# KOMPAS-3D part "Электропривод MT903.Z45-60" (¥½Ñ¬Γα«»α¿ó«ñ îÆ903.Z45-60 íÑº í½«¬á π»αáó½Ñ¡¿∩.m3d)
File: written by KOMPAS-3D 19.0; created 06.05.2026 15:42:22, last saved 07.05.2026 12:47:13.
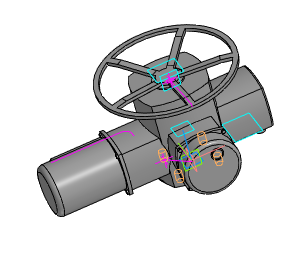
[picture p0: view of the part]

Document properties: Автор: Энергия; Полное имя файла: Z:\3.Личные\kachalov\3d для проектировщиков\2.2 Тип 47GVA, 47GVA.Z\Привод\Электропривод МТ903.Z45-60 без блока управления.m3d

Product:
- Part/product: Электропривод MT903.Z45-60
    Масса: 170.293

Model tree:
1. Эскиз:1
2. Элемент выдавливания:1
     Расстояние 1 = 274
3. Эскиз:2
4. Элемент выдавливания:2
     Расстояние 1 = 200
5. Эскиз:3  (with: Элемент выдавливания:2)
6. Элемент выдавливания:3
     Расстояние 1 = 10
7. Эскиз:4  (with: Элемент выдавливания:3)
8. Элемент выдавливания:4
     Расстояние 1 = 200
9. Скругление:1  (with: Элемент выдавливания:4)
     Радиус = 15
10. Эскиз:5
11. Элемент выдавливания:5
     Расстояние 1 = 170
12. Эскиз:6  (with: Элемент выдавливания:5)
13. Элемент выдавливания:6
     Расстояние 1 = 10
14. Эскиз:7  (with: Элемент выдавливания:6)
15. Элемент выдавливания:7
     Расстояние 1 = 50
16. Скругление:2  (with: Элемент выдавливания:7)
     Радиус = 10
17. Эскиз:8
18. Элемент выдавливания:8
     Расстояние 1 = 230
19. Скругление:3  (with: Элемент выдавливания:8)
     Радиус = 5
20. Касательная плоскость:1  (with: Элемент выдавливания:8)
21. Эскиз:10
22. Элемент выдавливания:9
     Расстояние 1 = 5
23. Эскиз:11  (with: Элемент выдавливания:9)
24. Отверстие:1  (with: Элемент выдавливания:9)  (labels: M20)
     Глубина выреза = 35; Диаметр отверстия = 17.2937; Угол конуса дна = 118; Расстояние 1 = -58.3363; Расстояние 2 = -58.3363
25. M20  (with: Элемент выдавливания:9)  (labels: M20; cil0_24705-2004 coarse)
     Длина резьбы = 30; Шаг резьбы = 2.5; Номинальный диаметр резьбы = 20
26. Массив по концентрической сетке:1  (with: Отверстие:1, Эскиз:11)  (labels: M20)  (2 pattern instances)
27. M10  (with: Отверстие:1, Элемент выдавливания:9, Эскиз:11)  (labels: M20; cil0_24705-2004 coarse)  (1 pattern instances)
     Длина резьбы = 30; Шаг резьбы = 2.5; Номинальный диаметр резьбы = 20
28. Отверстие:1  (with: Эскиз:11)  (labels: M20)
29. Эскиз:12  (with: Элемент выдавливания:9)
30. Элемент выдавливания:10
     Расстояние 1 = 5
31. Эскиз:13  (with: Элемент выдавливания:10)
32. Элемент выдавливания:11
     Расстояние 2 = 50
33. Эскиз:14
34. Элемент выдавливания:14  (with: Элемент выдавливания:8)
     Расстояние 1 = 15; Расстояние 2 = 10
35. Эскиз:15  (with: Элемент выдавливания:1)
36. Элемент выдавливания:15
     Расстояние 1 = 5
37. Эскиз:16  (with: Элемент выдавливания:15)
38. Смещенная плоскость:1  (with: Элемент выдавливания:15)
     Расстояние = 25
39. Эскиз:17  (with: Элемент выдавливания:15)
40. Элемент выдавливания:16
     Расстояние 1 = 10
41. Элемент выдавливания:17
     Расстояние 1 = 10
42. Эскиз:20  (with: Элемент выдавливания:16, Элемент выдавливания:17)
43. Перпендикулярная плоскость:1
44. Эскиз:21
45. Элемент по траектории:1
46. Массив по концентрической сетке:5  (with: Элемент по траектории:1, Эскиз:21, Элемент выдавливания:17)  (5 pattern instances)
     Шаг 2 = 360
47. Скругление:5  (with: Элемент выдавливания:14, Элемент выдавливания:7, Элемент выдавливания:4)
     Радиус = 1
48. Эскиз:22  (with: Элемент выдавливания:3, Скругление:5)
49. Элемент выдавливания:18
     Расстояние 1 = 5
50. Скругление:6  (with: Элемент выдавливания:18)
     Радиус = 1
51. Массив по концентрической сетке:3  (with: Элемент выдавливания:18, Эскиз:22, Скругление:6, Элемент выдавливания:4)  (4 pattern instances)
     Шаг 2 = 360
52. Эскиз:23  (with: Элемент выдавливания:6, Скругление:5)
53. Элемент выдавливания:19
     Расстояние 1 = 5
54. Скругление:7  (with: Элемент выдавливания:19)
     Радиус = 1
55. Массив по концентрической сетке:4  (with: Элемент выдавливания:19, Эскиз:23, Скругление:7, Элемент выдавливания:7)  (4 pattern instances)
     Шаг 2 = 360
56. Эскиз:24
57. Элемент выдавливания:20
     Расстояние 1 = 60
58. Смещенная плоскость:2
59. Эскиз:25  (with: Элемент выдавливания:20)
60. Эскиз:26  (with: Элемент выдавливания:20)
61. Элемент по траектории:2
62. Фаска:1  (with: Элемент по траектории:2)
     Угол = 45; Длина 1 = 2; Длина 2 = 2
63. Эскиз:27  (with: Элемент выдавливания:7)
64. Элемент выдавливания:21
     Расстояние 1 = 3
65. Эскиз:28  (with: Элемент выдавливания:21)
66. Элемент выдавливания:22
     Расстояние 2 = 1

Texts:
  Точка начала. Х
  Точка начала. Y
  Точка начала. Z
